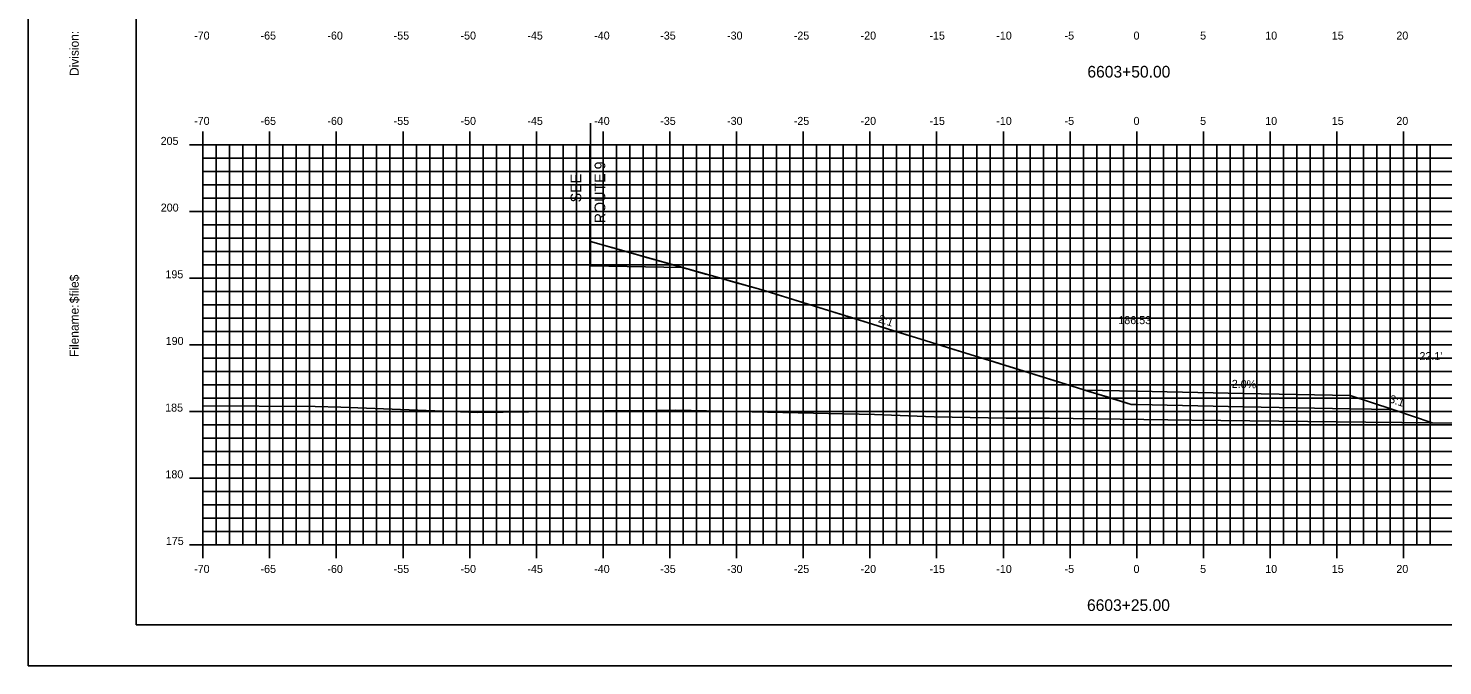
# Model space of a CAD drawing. Extents: x 1724627 to 1724798, y 459560 to 459670.
# Drawn here: x 1724626.6 to 1724732.7, y 459559.6 to 459607.4 of the extents above; entities that cross this region are included whole.
import ezdxf

# ---------------------------------------------------------------- set-up
doc = ezdxf.new("R2010")
doc.units = 0
for name, color, linetype in [('ANNOTATION', 7, 'Continuous'), ('BORDER', 7, 'Continuous'), ('D_Roadway_Centerline', 7, 'Continuous'), ('D_Roadway_Centerline_Text', 7, 'Continuous'), ('D_Roadway_Drive_Gravel', 7, 'Continuous'), ('D_Roadway_Edge_Shoulder', 7, 'Continuous'), ('D_Roadway_SlopeLines', 7, 'Continuous'), ('D_Roadway_SubGrade', 7, 'Continuous'), ('D_Text_Standard', 7, 'Continuous'), ('H_V ANNOTATION', 7, 'Continuous'), ('MAJOR', 7, 'Continuous'), ('MINOR', 7, 'Continuous'), ('PLOT BOUNDARY', 7, 'Continuous'), ('S_Roadway_Centerline', 7, 'Continuous')]:
    doc.layers.add(name, color=color, linetype=linetype)

msp = doc.modelspace()

# ---------------------------------------------------------------- linework, layer by layer
msp.add_lwpolyline([(1724709.74, 459580.14), (1724717.74, 459579.98), (1724725.74, 459579.82), (1724728.93, 459578.76), (1724731.89, 459577.77)])
at = {"layer": 'BORDER'}
msp.add_lwpolyline([(1724634.74, 459562.61), (1724794.74, 459562.61), (1724794.74, 459667.61), (1724634.74, 459667.61)], close=True, dxfattribs=at)
at = {"layer": 'D_Roadway_Centerline'}
msp.add_lwpolyline([(1724668.8, 459591.37), (1724669.93, 459591.04), (1724670.31, 459590.94), (1724671.81, 459590.51), (1724673, 459590.17), (1724673.85, 459589.93), (1724675.67, 459589.42), (1724676.02, 459589.31), (1724676.22, 459589.26), (1724677.42, 459588.92), (1724677.93, 459588.78), (1724679.45, 459588.35), (1724681.55, 459587.77), (1724682.06, 459587.61), (1724682.13, 459587.59), (1724682.83, 459587.37), (1724682.86, 459587.36), (1724686.95, 459586.1), (1724687.79, 459585.83), (1724687.99, 459585.77), (1724688.04, 459585.76), (1724691.27, 459584.75), (1724692.72, 459584.3), (1724693.48, 459584.07), (1724693.95, 459583.92), (1724695.96, 459583.3), (1724697.65, 459582.77), (1724698.66, 459582.46), (1724699.86, 459582.09), (1724700.91, 459581.76), (1724702.58, 459581.24), (1724703.54, 459580.94), (1724705.77, 459580.25), (1724706.15, 459580.13), (1724707.51, 459579.71), (1724708.16, 459579.51), (1724709.32, 459579.15)], dxfattribs=at)
at = {"layer": 'D_Roadway_Drive_Gravel'}
msp.add_lwpolyline([(1724709.74, 459580.14), (1724717.74, 459579.98), (1724725.74, 459579.82), (1724728.93, 459578.76), (1724725.74, 459578.82), (1724717.74, 459578.98), (1724709.74, 459579.14)], dxfattribs=at)
at = {"layer": 'D_Roadway_Edge_Shoulder'}
msp.add_line((1724668.8, 459591.37), (1724668.8, 459591.12), dxfattribs=at)
msp.add_line((1724668.8, 459591.37), (1724668.8, 459591.12), dxfattribs=at)
at = {"layer": 'D_Roadway_SlopeLines'}
for points in [[(1724668.8, 459591.37), (1724681.55, 459587.77), (1724709.32, 459579.15)], [(1724668.8, 459591.37), (1724681.55, 459587.77), (1724709.32, 459579.15)], [(1724668.8, 459591.37), (1724681.55, 459587.77), (1724709.32, 459579.15)], [(1724668.8, 459591.37), (1724681.55, 459587.77), (1724709.32, 459579.15)], [(1724668.8, 459591.37), (1724681.55, 459587.77), (1724709.32, 459579.15)], [(1724668.8, 459591.37), (1724681.55, 459587.77), (1724709.32, 459579.15)], [(1724668.8, 459591.37), (1724681.55, 459587.77), (1724709.32, 459579.15)], [(1724725.74, 459579.82), (1724728.93, 459578.76), (1724731.89, 459577.77)]]:
    msp.add_lwpolyline(points, dxfattribs=at)
at = {"layer": 'D_Roadway_SubGrade'}
for p, q in [((1724668.8, 459600.23), (1724668.8, 459589.55)), ((1724709.74, 459580.14), (1724705.88, 459580.22)), ((1724709.74, 459579.14), (1724709.32, 459579.15))]:
    msp.add_line(p, q, dxfattribs=at)
msp.add_lwpolyline([(1724668.8, 459591.12), (1724668.8, 459591.37), (1724675.67, 459589.42), (1724668.8, 459589.55)], dxfattribs=at)
msp.add_lwpolyline([(1724668.8, 459591.12), (1724668.8, 459591.37), (1724675.67, 459589.42), (1724668.8, 459589.55)], dxfattribs=at)
at = {"layer": 'MAJOR'}
for p, q in [((1724639.74, 459599.61), (1724639.74, 459598.61)), ((1724644.74, 459599.61), (1724644.74, 459598.61)), ((1724649.74, 459599.61), (1724649.74, 459598.61)), ((1724654.74, 459599.61), (1724654.74, 459598.61)), ((1724659.74, 459599.61), (1724659.74, 459598.61)), ((1724664.74, 459599.61), (1724664.74, 459598.61)), ((1724669.74, 459599.61), (1724669.74, 459598.61)), ((1724674.74, 459599.61), (1724674.74, 459598.61)), ((1724679.74, 459599.61), (1724679.74, 459598.61)), ((1724684.74, 459599.61), (1724684.74, 459598.61)), ((1724689.74, 459599.61), (1724689.74, 459598.61)), ((1724694.74, 459599.61), (1724694.74, 459598.61)), ((1724699.74, 459599.61), (1724699.74, 459598.61)), ((1724704.74, 459599.61), (1724704.74, 459598.61)), ((1724709.74, 459599.61), (1724709.74, 459598.61)), ((1724714.74, 459599.61), (1724714.74, 459598.61)), ((1724719.74, 459599.61), (1724719.74, 459598.61)), ((1724724.74, 459599.61), (1724724.74, 459598.61)), ((1724729.74, 459599.61), (1724729.74, 459598.61)), ((1724638.74, 459598.61), (1724639.74, 459598.61)), ((1724639.74, 459598.61), (1724779.74, 459598.61)), ((1724639.74, 459568.61), (1724639.74, 459598.61)), ((1724639.74, 459568.61), (1724639.74, 459598.61)), ((1724639.74, 459598.61), (1724779.74, 459598.61)), ((1724644.74, 459568.61), (1724644.74, 459598.61)), ((1724649.74, 459568.61), (1724649.74, 459598.61)), ((1724654.74, 459568.61), (1724654.74, 459598.61)), ((1724659.74, 459568.61), (1724659.74, 459598.61)), ((1724664.74, 459568.61), (1724664.74, 459598.61)), ((1724669.74, 459568.61), (1724669.74, 459598.61)), ((1724674.74, 459568.61), (1724674.74, 459598.61)), ((1724679.74, 459568.61), (1724679.74, 459598.61)), ((1724684.74, 459568.61), (1724684.74, 459598.61)), ((1724689.74, 459568.61), (1724689.74, 459598.61)), ((1724694.74, 459568.61), (1724694.74, 459598.61)), ((1724699.74, 459568.61), (1724699.74, 459598.61)), ((1724704.74, 459568.61), (1724704.74, 459598.61)), ((1724709.74, 459568.61), (1724709.74, 459598.61)), ((1724714.74, 459568.61), (1724714.74, 459598.61)), ((1724719.74, 459568.61), (1724719.74, 459598.61)), ((1724724.74, 459568.61), (1724724.74, 459598.61)), ((1724729.74, 459568.61), (1724729.74, 459598.61)), ((1724638.74, 459593.61), (1724639.74, 459593.61)), ((1724639.74, 459593.61), (1724779.74, 459593.61)), ((1724638.74, 459588.61), (1724639.74, 459588.61)), ((1724639.74, 459588.61), (1724779.74, 459588.61)), ((1724638.74, 459583.61), (1724639.74, 459583.61)), ((1724639.74, 459583.61), (1724779.74, 459583.61)), ((1724638.74, 459578.61), (1724639.74, 459578.61)), ((1724639.74, 459578.61), (1724779.74, 459578.61)), ((1724638.74, 459573.61), (1724639.74, 459573.61)), ((1724639.74, 459573.61), (1724779.74, 459573.61)), ((1724638.74, 459568.61), (1724639.74, 459568.61)), ((1724639.74, 459568.61), (1724779.74, 459568.61)), ((1724639.74, 459568.61), (1724779.74, 459568.61)), ((1724639.74, 459567.61), (1724639.74, 459568.61)), ((1724644.74, 459567.61), (1724644.74, 459568.61)), ((1724649.74, 459567.61), (1724649.74, 459568.61)), ((1724654.74, 459567.61), (1724654.74, 459568.61)), ((1724659.74, 459567.61), (1724659.74, 459568.61)), ((1724664.74, 459567.61), (1724664.74, 459568.61)), ((1724669.74, 459567.61), (1724669.74, 459568.61)), ((1724674.74, 459567.61), (1724674.74, 459568.61)), ((1724679.74, 459567.61), (1724679.74, 459568.61)), ((1724684.74, 459567.61), (1724684.74, 459568.61)), ((1724689.74, 459567.61), (1724689.74, 459568.61)), ((1724694.74, 459567.61), (1724694.74, 459568.61)), ((1724699.74, 459567.61), (1724699.74, 459568.61)), ((1724704.74, 459567.61), (1724704.74, 459568.61)), ((1724709.74, 459567.61), (1724709.74, 459568.61)), ((1724714.74, 459567.61), (1724714.74, 459568.61)), ((1724719.74, 459567.61), (1724719.74, 459568.61)), ((1724724.74, 459567.61), (1724724.74, 459568.61)), ((1724729.74, 459567.61), (1724729.74, 459568.61))]:
    msp.add_line(p, q, dxfattribs=at)
at = {"layer": 'MINOR'}
for p, q in [((1724640.74, 459568.61), (1724640.74, 459598.61)), ((1724641.74, 459568.61), (1724641.74, 459598.61)), ((1724642.74, 459568.61), (1724642.74, 459598.61)), ((1724643.74, 459568.61), (1724643.74, 459598.61)), ((1724645.74, 459568.61), (1724645.74, 459598.61)), ((1724646.74, 459568.61), (1724646.74, 459598.61)), ((1724647.74, 459568.61), (1724647.74, 459598.61)), ((1724648.74, 459568.61), (1724648.74, 459598.61)), ((1724650.74, 459568.61), (1724650.74, 459598.61)), ((1724651.74, 459568.61), (1724651.74, 459598.61)), ((1724652.74, 459568.61), (1724652.74, 459598.61)), ((1724653.74, 459568.61), (1724653.74, 459598.61)), ((1724655.74, 459568.61), (1724655.74, 459598.61)), ((1724656.74, 459568.61), (1724656.74, 459598.61)), ((1724657.74, 459568.61), (1724657.74, 459598.61)), ((1724658.74, 459568.61), (1724658.74, 459598.61)), ((1724660.74, 459568.61), (1724660.74, 459598.61)), ((1724661.74, 459568.61), (1724661.74, 459598.61)), ((1724662.74, 459568.61), (1724662.74, 459598.61)), ((1724663.74, 459568.61), (1724663.74, 459598.61)), ((1724665.74, 459568.61), (1724665.74, 459598.61)), ((1724666.74, 459568.61), (1724666.74, 459598.61)), ((1724667.74, 459568.61), (1724667.74, 459598.61)), ((1724668.74, 459568.61), (1724668.74, 459598.61)), ((1724670.74, 459568.61), (1724670.74, 459598.61)), ((1724671.74, 459568.61), (1724671.74, 459598.61)), ((1724672.74, 459568.61), (1724672.74, 459598.61)), ((1724673.74, 459568.61), (1724673.74, 459598.61)), ((1724675.74, 459568.61), (1724675.74, 459598.61)), ((1724676.74, 459568.61), (1724676.74, 459598.61)), ((1724677.74, 459568.61), (1724677.74, 459598.61)), ((1724678.74, 459568.61), (1724678.74, 459598.61)), ((1724680.74, 459568.61), (1724680.74, 459598.61)), ((1724681.74, 459568.61), (1724681.74, 459598.61)), ((1724682.74, 459568.61), (1724682.74, 459598.61)), ((1724683.74, 459568.61), (1724683.74, 459598.61)), ((1724685.74, 459568.61), (1724685.74, 459598.61)), ((1724686.74, 459568.61), (1724686.74, 459598.61)), ((1724687.74, 459568.61), (1724687.74, 459598.61)), ((1724688.74, 459568.61), (1724688.74, 459598.61)), ((1724690.74, 459568.61), (1724690.74, 459598.61)), ((1724691.74, 459568.61), (1724691.74, 459598.61)), ((1724692.74, 459568.61), (1724692.74, 459598.61)), ((1724693.74, 459568.61), (1724693.74, 459598.61)), ((1724695.74, 459568.61), (1724695.74, 459598.61)), ((1724696.74, 459568.61), (1724696.74, 459598.61)), ((1724697.74, 459568.61), (1724697.74, 459598.61)), ((1724698.74, 459568.61), (1724698.74, 459598.61)), ((1724700.74, 459568.61), (1724700.74, 459598.61)), ((1724701.74, 459568.61), (1724701.74, 459598.61)), ((1724702.74, 459568.61), (1724702.74, 459598.61)), ((1724703.74, 459568.61), (1724703.74, 459598.61)), ((1724705.74, 459568.61), (1724705.74, 459598.61)), ((1724706.74, 459568.61), (1724706.74, 459598.61)), ((1724707.74, 459568.61), (1724707.74, 459598.61)), ((1724708.74, 459568.61), (1724708.74, 459598.61)), ((1724710.74, 459568.61), (1724710.74, 459598.61)), ((1724711.74, 459568.61), (1724711.74, 459598.61)), ((1724712.74, 459568.61), (1724712.74, 459598.61)), ((1724713.74, 459568.61), (1724713.74, 459598.61)), ((1724715.74, 459568.61), (1724715.74, 459598.61)), ((1724716.74, 459568.61), (1724716.74, 459598.61)), ((1724717.74, 459568.61), (1724717.74, 459598.61)), ((1724718.74, 459568.61), (1724718.74, 459598.61)), ((1724720.74, 459568.61), (1724720.74, 459598.61)), ((1724721.74, 459568.61), (1724721.74, 459598.61)), ((1724722.74, 459568.61), (1724722.74, 459598.61)), ((1724723.74, 459568.61), (1724723.74, 459598.61)), ((1724725.74, 459568.61), (1724725.74, 459598.61)), ((1724726.74, 459568.61), (1724726.74, 459598.61)), ((1724727.74, 459568.61), (1724727.74, 459598.61)), ((1724728.74, 459568.61), (1724728.74, 459598.61)), ((1724730.74, 459568.61), (1724730.74, 459598.61)), ((1724731.74, 459568.61), (1724731.74, 459598.61)), ((1724639.74, 459597.61), (1724779.74, 459597.61)), ((1724639.74, 459597.61), (1724640.74, 459597.61)), ((1724639.74, 459596.61), (1724779.74, 459596.61)), ((1724639.74, 459596.61), (1724640.74, 459596.61)), ((1724639.74, 459595.61), (1724779.74, 459595.61)), ((1724639.74, 459595.61), (1724640.74, 459595.61)), ((1724639.74, 459594.61), (1724779.74, 459594.61)), ((1724639.74, 459594.61), (1724640.74, 459594.61)), ((1724639.74, 459592.61), (1724779.74, 459592.61)), ((1724639.74, 459592.61), (1724640.74, 459592.61)), ((1724639.74, 459591.61), (1724779.74, 459591.61)), ((1724639.74, 459591.61), (1724640.74, 459591.61)), ((1724639.74, 459590.61), (1724779.74, 459590.61)), ((1724639.74, 459590.61), (1724640.74, 459590.61)), ((1724639.74, 459589.61), (1724779.74, 459589.61)), ((1724639.74, 459589.61), (1724640.74, 459589.61)), ((1724639.74, 459587.61), (1724779.74, 459587.61)), ((1724639.74, 459587.61), (1724640.74, 459587.61)), ((1724639.74, 459586.61), (1724779.74, 459586.61)), ((1724639.74, 459586.61), (1724640.74, 459586.61)), ((1724639.74, 459585.61), (1724779.74, 459585.61)), ((1724639.74, 459585.61), (1724640.74, 459585.61)), ((1724639.74, 459584.61), (1724779.74, 459584.61)), ((1724639.74, 459584.61), (1724640.74, 459584.61)), ((1724639.74, 459582.61), (1724779.74, 459582.61)), ((1724639.74, 459582.61), (1724640.74, 459582.61)), ((1724639.74, 459581.61), (1724779.74, 459581.61)), ((1724639.74, 459581.61), (1724640.74, 459581.61)), ((1724639.74, 459580.61), (1724779.74, 459580.61)), ((1724639.74, 459580.61), (1724640.74, 459580.61)), ((1724639.74, 459579.61), (1724779.74, 459579.61)), ((1724639.74, 459579.61), (1724640.74, 459579.61)), ((1724639.74, 459577.61), (1724779.74, 459577.61)), ((1724639.74, 459577.61), (1724640.74, 459577.61)), ((1724639.74, 459576.61), (1724779.74, 459576.61)), ((1724639.74, 459576.61), (1724640.74, 459576.61)), ((1724639.74, 459575.61), (1724779.74, 459575.61)), ((1724639.74, 459575.61), (1724640.74, 459575.61)), ((1724639.74, 459574.61), (1724779.74, 459574.61)), ((1724639.74, 459574.61), (1724640.74, 459574.61)), ((1724639.74, 459572.61), (1724779.74, 459572.61)), ((1724639.74, 459572.61), (1724640.74, 459572.61)), ((1724639.74, 459571.61), (1724779.74, 459571.61)), ((1724639.74, 459571.61), (1724640.74, 459571.61)), ((1724639.74, 459570.61), (1724779.74, 459570.61)), ((1724639.74, 459570.61), (1724640.74, 459570.61)), ((1724639.74, 459569.61), (1724779.74, 459569.61)), ((1724639.74, 459569.61), (1724640.74, 459569.61))]:
    msp.add_line(p, q, dxfattribs=at)
at = {"layer": 'PLOT BOUNDARY'}
msp.add_lwpolyline([(1724626.65, 459559.55), (1724796.65, 459559.55), (1724796.65, 459669.55), (1724626.65, 459669.55)], close=True, dxfattribs=at)
at = {"layer": 'S_Roadway_Centerline'}
msp.add_lwpolyline([(1724639.74, 459579.05), (1724648.15, 459579), (1724650.09, 459578.95), (1724660.33, 459578.55), (1724669.88, 459578.67), (1724672.27, 459578.67), (1724675.18, 459578.72), (1724690.09, 459578.39), (1724694.55, 459578.21), (1724699.96, 459578.11), (1724703.21, 459578.13), (1724710.28, 459578.02), (1724713.86, 459577.97), (1724726.92, 459577.81), (1724729.62, 459577.8), (1724731.76, 459577.77), (1724742.12, 459577.7), (1724753.42, 459577.35), (1724755.89, 459577.31), (1724762.13, 459577.2), (1724775.36, 459576.96), (1724777.4, 459576.94), (1724779.74, 459577.02)], dxfattribs=at)

# ---------------------------------------------------------------- texts
at = {"layer": 'ANNOTATION'}
for s, height, rotation, p in [('SEE', 0.8, 90, (1724668.1, 459594.3)), ('ROUTE 9', 0.8, 90, (1724669.9, 459592.73)), ('2:1', 0.6, 341.5651, (1724690.31, 459585.33)), ('-2.0%', 0.6, 358.8542, (1724716.59, 459580.4)), ('3:1', 0.6, 341.5651, (1724728.62, 459579.32))]:
    msp.add_text(s, height=height, rotation=rotation, dxfattribs=at).set_placement(p)
at = {"layer": 'BORDER'}
for s, p in [('Division:', (1724630.43, 459603.78)), ('$file$', (1724630.43, 459586.74)), ('Filename:', (1724630.43, 459582.71))]:
    msp.add_text(s, height=0.67, rotation=90, dxfattribs=at).set_placement(p)
at = {"layer": 'D_Roadway_Centerline_Text'}
msp.add_text('186.53', height=0.6, dxfattribs=at).set_placement((1724708.36, 459585.17))
at = {"layer": 'D_Text_Standard'}
msp.add_text("22.1'", height=0.6, dxfattribs=at).set_placement((1724730.93, 459582.47))
at = {"layer": 'H_V ANNOTATION'}
for s, height, p in [('-70', 0.6, (1724639.08, 459606.51)), ('-65', 0.6, (1724644.06, 459606.51)), ('-60', 0.6, (1724649.07, 459606.51)), ('-55', 0.6, (1724654.04, 459606.51)), ('-50', 0.6, (1724659.05, 459606.51)), ('-45', 0.6, (1724664.06, 459606.51)), ('-40', 0.6, (1724669.07, 459606.51)), ('-35', 0.6, (1724674.02, 459606.51)), ('-30', 0.6, (1724679.03, 459606.51)), ('-25', 0.6, (1724684.03, 459606.51)), ('-20', 0.6, (1724689.04, 459606.51)), ('-15', 0.6, (1724694.2, 459606.51)), ('-10', 0.6, (1724699.21, 459606.51)), ('-5', 0.6, (1724704.33, 459606.51)), ('0', 0.6, (1724709.5, 459606.51)), ('5', 0.6, (1724714.49, 459606.51)), ('10', 0.6, (1724719.37, 459606.51)), ('15', 0.6, (1724724.36, 459606.51)), ('20', 0.6, (1724729.2, 459606.51)), ('6603+50.00', 0.875, (1724706.04, 459603.66)), ('-70', 0.6, (1724639.08, 459600.11)), ('-65', 0.6, (1724644.06, 459600.11)), ('-60', 0.6, (1724649.07, 459600.11)), ('-55', 0.6, (1724654.04, 459600.11)), ('-50', 0.6, (1724659.05, 459600.11)), ('-45', 0.6, (1724664.06, 459600.11)), ('-40', 0.6, (1724669.07, 459600.11)), ('-35', 0.6, (1724674.02, 459600.11)), ('-30', 0.6, (1724679.03, 459600.11)), ('-25', 0.6, (1724684.03, 459600.11)), ('-20', 0.6, (1724689.04, 459600.11)), ('-15', 0.6, (1724694.2, 459600.11)), ('-10', 0.6, (1724699.21, 459600.11)), ('-5', 0.6, (1724704.33, 459600.11)), ('0', 0.6, (1724709.5, 459600.11)), ('5', 0.6, (1724714.49, 459600.11)), ('10', 0.6, (1724719.37, 459600.11)), ('15', 0.6, (1724724.36, 459600.11)), ('20', 0.6, (1724729.2, 459600.11)), ('205', 0.6, (1724636.57, 459598.61)), ('200', 0.6, (1724636.58, 459593.61)), ('195', 0.6, (1724636.93, 459588.61)), ('190', 0.6, (1724636.95, 459583.61)), ('185', 0.6, (1724636.91, 459578.61)), ('180', 0.6, (1724636.93, 459573.61)), ('175', 0.6, (1724636.96, 459568.61)), ('-70', 0.6, (1724639.08, 459566.51)), ('-65', 0.6, (1724644.06, 459566.51)), ('-60', 0.6, (1724649.07, 459566.51)), ('-55', 0.6, (1724654.04, 459566.51)), ('-50', 0.6, (1724659.05, 459566.51)), ('-45', 0.6, (1724664.06, 459566.51)), ('-40', 0.6, (1724669.07, 459566.51)), ('-35', 0.6, (1724674.02, 459566.51)), ('-30', 0.6, (1724679.03, 459566.51)), ('-25', 0.6, (1724684.03, 459566.51)), ('-20', 0.6, (1724689.04, 459566.51)), ('-15', 0.6, (1724694.2, 459566.51)), ('-10', 0.6, (1724699.21, 459566.51)), ('-5', 0.6, (1724704.33, 459566.51)), ('0', 0.6, (1724709.5, 459566.51)), ('5', 0.6, (1724714.49, 459566.51)), ('10', 0.6, (1724719.37, 459566.51)), ('15', 0.6, (1724724.36, 459566.51)), ('20', 0.6, (1724729.2, 459566.51)), ('6603+25.00', 0.875, (1724706.01, 459563.66))]:
    msp.add_text(s, height=height, dxfattribs=at).set_placement(p)
at = {"layer": 'MAJOR'}
msp.add_text('-', height=0.006, dxfattribs=at).set_placement((1724639.74, 459568.61))

doc.saveas('drawing.dxf')
